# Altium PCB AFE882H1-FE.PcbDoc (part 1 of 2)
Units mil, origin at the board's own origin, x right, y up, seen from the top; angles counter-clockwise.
Board outline 2755.91 x 1181.1 mil, 4 copper layers (Top Layer, Int1 (GND), Int2 (PWR), Bottom Layer), stack 53.912 mil thick; 80 components, 47 nets, 216 pads, 76 vias.
Unrouted connection lines stored in the file: 4.
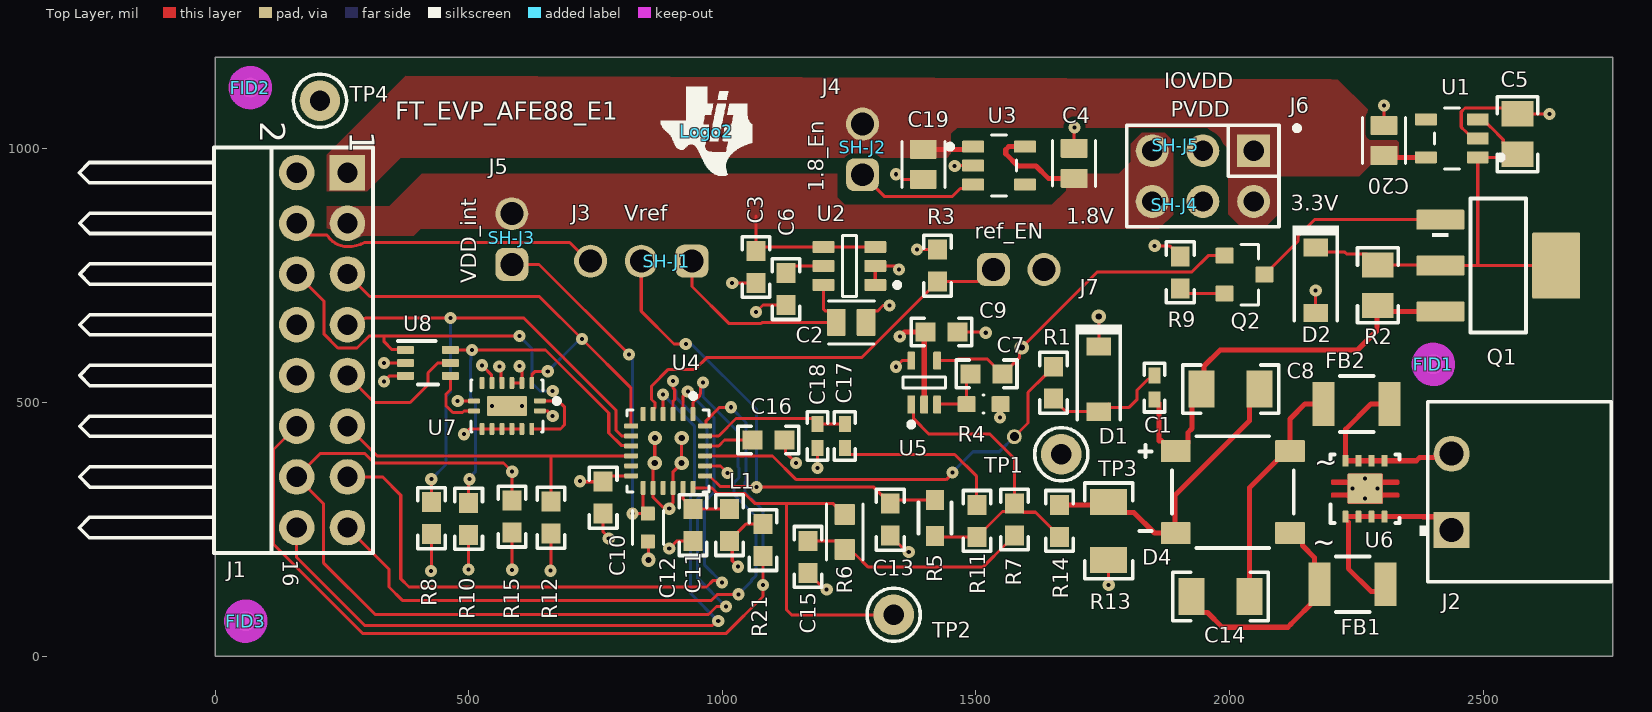
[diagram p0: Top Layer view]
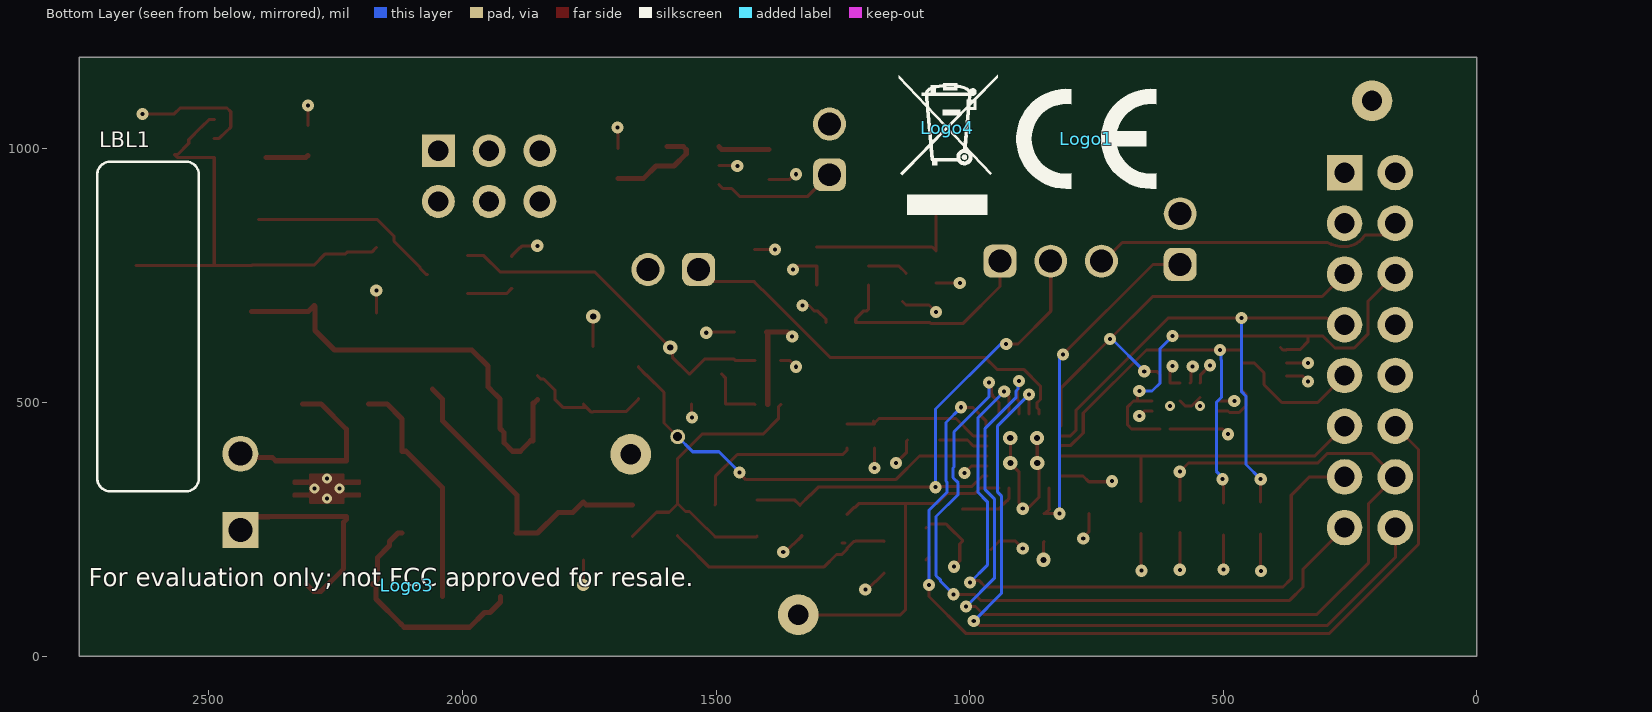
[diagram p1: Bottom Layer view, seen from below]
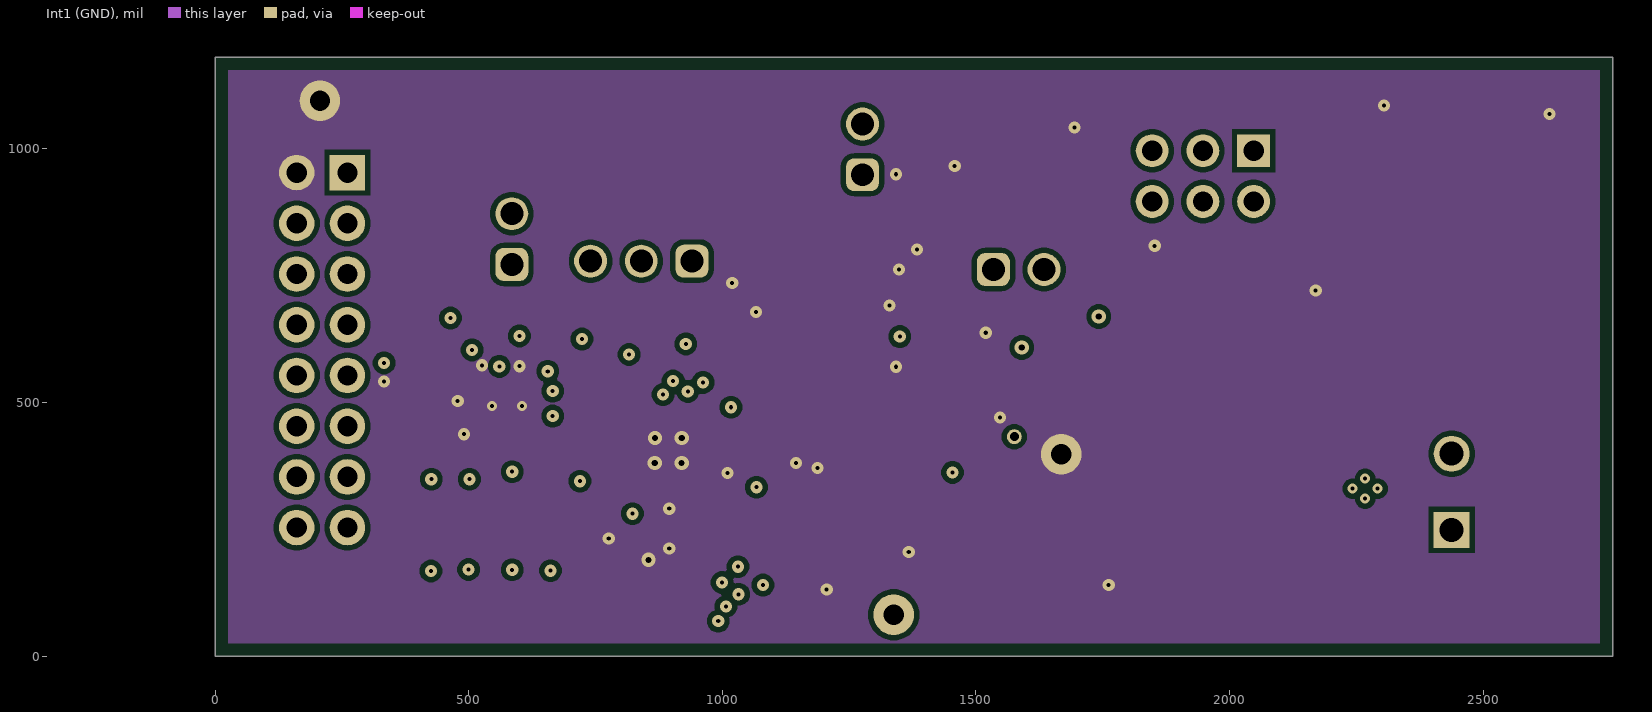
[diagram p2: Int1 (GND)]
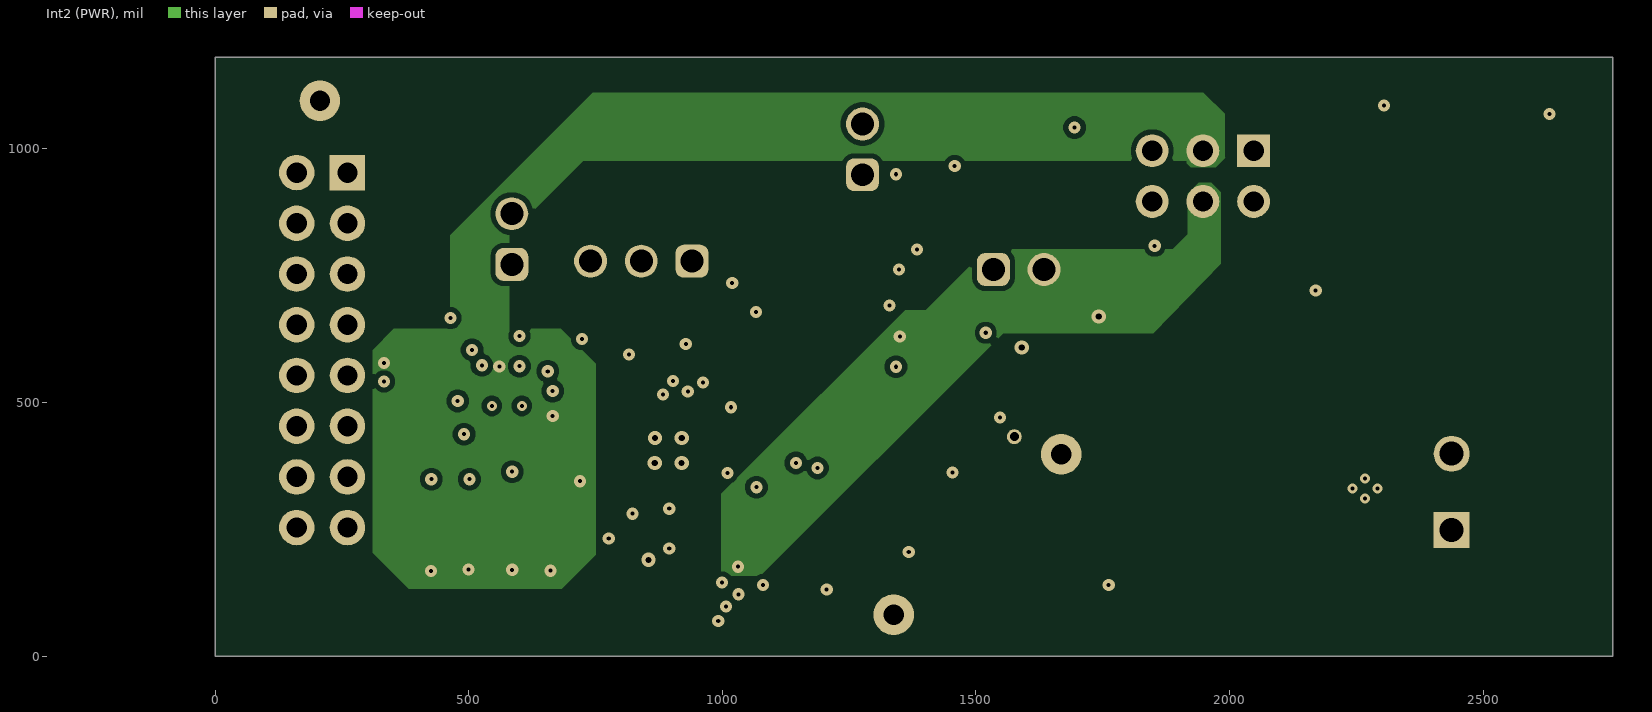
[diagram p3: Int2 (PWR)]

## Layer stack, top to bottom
Top Solder: solder mask 1, SM-001, Dk 4
Top Layer: signal copper 1.378
Dielectric 1: prepreg 5.1, PP-017, Dk 4.3
Dielectric 2: prepreg 5.1, PP-017, Dk 4.3
Int1 (GND): signal copper 1.378
Dielectric 3: core 28, Core-039, Dk 4.8
Int2 (PWR): signal copper 1.378
Dielectric 4: prepreg 5.1, PP-017, Dk 4.3
Dielectric 5: prepreg 5.1, PP-017, Dk 4.3
Bottom Layer: signal copper 1.378
Bottom Solder: solder mask 1, SM-001, Dk 4

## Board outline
0,0 2755.91,0 2755.91,1181.1 0,1181.1

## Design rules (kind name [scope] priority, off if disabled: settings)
AcuteAngle [All] p1 off: minimum=4.50000000000000E+0001 checktracksonly=FALSE
AssemblyTestPointUsage [All] p1: valid=2
BoardOutlineClearance BoardOutlineClearance_MountingHoles [OnCopper and InComponentClass('Mounting Holes')] p1: gap=39.37 ignorepadtopadclearanceinfootprint=FALSE
BoardOutlineClearance BoardOutlineClearance_Poly [OnCopper and IsPoly] p2: gap=25 ignorepadtopadclearanceinfootprint=FALSE
BoardOutlineClearance [OnCopper and Not InComponentClass('Logo') and not InComponentClass('FiducialMark') and not InRegion(1000,500,4000,800) and not InPoly] p3: gap=40 ignorepadtopadclearanceinfootprint=FALSE
Clearance Clearance_Keepouts [((IsTrack Or IsArc) And Not InPoly) And IsFree and IsKeepOut vs ((IsTrack Or IsArc) And Not InPoly) And IsFree and IsKeepOut] p1: gap=0 ignorepadtopadclearanceinfootprint=FALSE
Clearance Clearance_Poly [InPolygon] p2: gap=10 ignorepadtopadclearanceinfootprint=TRUE
Clearance Clearance_FiducialMark [IsKeepOut and InComponentClass('FiducialMark') vs IsPad and InComponentClass('FiducialMark')] p3: gap=0 ignorepadtopadclearanceinfootprint=FALSE
Clearance [All] p4: gap=7.87 ignorepadtopadclearanceinfootprint=TRUE
ComponentClearance ComponentClearance_MountingHoles_FiducialMarks [InComponentClass('Mounting Holes') vs InComponentClass('FiducialMark')] p1: gap=50 collisioncheckmode=3 verticalgap=10 showdistances=FALSE
ComponentClearance ComponentClearance_Shunt [InComponentClass('Header') vs InComponentClass('Shunt')] p2: gap=0 collisioncheckmode=3 verticalgap=0 showdistances=FALSE
ComponentClearance ComponentClearance_Logo [InComponentClass('Logo')] p3: gap=30 collisioncheckmode=3 verticalgap=10 showdistances=FALSE
ComponentClearance ComponentClearance_ScrewToNut [(HasFootprint('NY PMS 440 0025 PH')) vs (HasFootprint('Keystone_1902C'))] p4: gap=5 collisioncheckmode=3 verticalgap=10 showdistances=FALSE
ComponentClearance ComponentClearance_MountingHoles [InComponentClass('Mounting Holes')] p5: gap=100 collisioncheckmode=3 verticalgap=100000 showdistances=FALSE
ComponentClearance ComponentClearance_SmallPassives [HasFootprint('0201*') or HasFootprint('0402*') or HasFootprint('0508') or HasFootprint('0603*') or HasFootprint('0612') or HasFootprint('0805*') or HasFootprint('0815*') or HasFootprint('0830*') or HasFootprint('1206*') or HasFootprint('1210*') or HasFootprint('1808*') or HasFootprint('1812*') or HasFootprint('1825*') or HasFootprint('2010*') or HasFootprint('2220*') or HasFootprint('2225*') or HasFootprint('2512*') or HasFootprint('2728*') or HasFootprint('3518*') vs HasFootprint('0201*') or HasFootprint('0402*') or HasFootprint('0508') or HasFootprint('0603*') or HasFootprint('0612') or HasFootprint('0805*') or HasFootprint('0815*') or HasFootprint('0830*') or HasFootprint('1206*') or HasFootprint('1210*') or HasFootprint('1808*') or HasFootprint('1812*') or HasFootprint('1825*') or HasFootprint('2010*') or HasFootprint('2220*') or HasFootprint('2225*') or HasFootprint('2512*') or HasFootprint('2728*') or HasFootprint('3518*')] p6: gap=14.96 collisioncheckmode=3 verticalgap=10 showdistances=FALSE
ComponentClearance ComponentClearance_THtoSMT [IsThruComponent vs IsSMTComponent] p7: gap=30 collisioncheckmode=3 verticalgap=30 showdistances=FALSE
ComponentClearance ComponentClearance_THtoTH [IsThruComponent vs IsThruComponent] p8: gap=20 collisioncheckmode=3 verticalgap=30 showdistances=FALSE
ComponentClearance [All] p9: gap=20 collisioncheckmode=3 verticalgap=10 showdistances=FALSE
DiffPairsRouting [All] p1: maxlimit=100 minlimit=10 mostfreqgap=10 toplayer_minwidth=15 toplayer_maxwidth=15 toplayer_prefwidth=15 midlayer1_minwidth=15 midlayer1_maxwidth=15 midlayer1_prefwidth=15 midlayer2_minwidth=15 midlayer2_maxwidth=15 midlayer2_prefwidth=15 bottomlayer_minwidth=15 bottomlayer_maxwidth=15 bottomlayer_prefwidth=15 maxuncoupledlength=1000
FabricationTestPointUsage TestPointUsage [All] p1: valid=2 allowmultiple=FALSE
FabricationTestpoint Testpoint [All] p1: side=3 testpointundercomponent=TRUE minsize=40 maxsize=100 preferedsize=60 minholesize=0 maxholesize=40 preferedholesize=32 testpointgrid=1 allowsidetop=TRUE allowsidebottom=TRUE usegrid=TRUE gridtolerance=0.01
FanoutControl Fanout_LCC [IsLCC] p1: bgadir=Out bgaviamode=Centered fanoutstyle=Auto fanoutdirection=Alternating viagrid=1 // Fanout_LCC (Default Rule)
FanoutControl Fanout_BGA [IsBGA] p2: bgadir=Out bgaviamode=Centered fanoutstyle=Auto fanoutdirection=Alternating viagrid=1 // Fanout_BGA (Default Rule)
FanoutControl Fanout_Default [All] p4: bgadir=Out bgaviamode=Centered fanoutstyle=Auto fanoutdirection=Alternating viagrid=1 // Fanout_Default (Default Rule)
FanoutControl Fanout_Small [(CompPinCount < 5)] p5: bgadir=Out bgaviamode=Centered fanoutstyle=Auto fanoutdirection=OutThenIn viagrid=1 // Fanout_Small (Default Rule)
HoleSize [All] p1: absolutevalues=TRUE maxlimit=251 minlimit=7.87 maxpercent=80.000 minpercent=20.000
MinimumAnnularRing MinimumAnnularRing_ThermalPadVias [IsVia and InAnyComponent] p1: minimumring=5.91
MinimumAnnularRing [All] p2: minimumring=7.87
MinimumSolderMaskSliver MinimumSolderMaskSliver_Logo [InComponentClass('Logo') vs InComponentClass('Logo')] p1: minsoldermaskwidth=0.7
MinimumSolderMaskSliver [All] p2: minsoldermaskwidth=3.94
PlaneConnect [All] p1: planeconnectstyle=Relief reliefexpansion=10 reliefentries=4 reliefconductorwidth=10 reliefairgap=10
PolygonConnect PolygonConnect_6 [All vs IsNamedPolygon('TOP_LAYER_GND_P000')] p1: connectstyle=Direct reliefconductorwidth=10 reliefentries=4 polygonreliefangle="90 Angle" airgapwidth=10
PolygonConnect PolygonConnect_5 [All vs IsNamedPolygon('TOP_LAYER_GND_P000')] p2: connectstyle=Direct reliefconductorwidth=10 reliefentries=4 polygonreliefangle="90 Angle" airgapwidth=10
PolygonConnect PolygonConnect_4 [All vs IsNamedPolygon('TOP_LAYER_GND_P001')] p3: connectstyle=Direct reliefconductorwidth=10 reliefentries=4 polygonreliefangle="90 Angle" airgapwidth=10
PolygonConnect PolygonConnect_3 [All vs IsNamedPolygon('TOP_LAYER_GND_P001')] p4: thpad.connectstyle=Direct thpad.reliefconductorwidth=10 thpad.reliefentries=4 thpad.polygonreliefangle="90 Angle" thpad.airgapwidth=10 smdpad.connectstyle=Direct smdpad.reliefconductorwidth=10 smdpad.reliefentries=4 smdpad.polygonreliefangle="90 Angle" smdpad.airgapwidth=10 via.connectstyle=Relief via.reliefconductorwidth=10 via.reliefentries=4 via.polygonreliefangle="90 Angle" via.airgapwidth=10
PolygonConnect PolygonConnect_2 [All vs IsNamedPolygon('TOP_LAYER_NONET_P000')] p5: thpad.connectstyle=Direct thpad.reliefconductorwidth=10 thpad.reliefentries=4 thpad.polygonreliefangle="90 Angle" thpad.airgapwidth=10 smdpad.connectstyle=Direct smdpad.reliefconductorwidth=10 smdpad.reliefentries=4 smdpad.polygonreliefangle="90 Angle" smdpad.airgapwidth=10 via.connectstyle=Relief via.reliefconductorwidth=10 via.reliefentries=4 via.polygonreliefangle="90 Angle" via.airgapwidth=10
PolygonConnect PolygonConnect_1 [All vs IsNamedPolygon('TOP_LAYER_NONET_P000')] p6: thpad.connectstyle=Direct thpad.reliefconductorwidth=10 thpad.reliefentries=4 thpad.polygonreliefangle="90 Angle" thpad.airgapwidth=10 smdpad.connectstyle=Direct smdpad.reliefconductorwidth=10 smdpad.reliefentries=4 smdpad.polygonreliefangle="90 Angle" smdpad.airgapwidth=10 via.connectstyle=Relief via.reliefconductorwidth=10 via.reliefentries=4 via.polygonreliefangle="90 Angle" via.airgapwidth=10
PolygonConnect [All] p7: connectstyle=Direct reliefconductorwidth=10 reliefentries=4 polygonreliefangle="90 Angle" airgapwidth=10
RoutingLayers [All] p1: top layer_v5=TRUE mid layer 1_v5=FALSE mid layer 2_v5=FALSE bottom layer_v5=TRUE
RoutingVias ThermalPadVias [IsVia and InAnyComponent] p1: holewidth=7.87 width=19.68 viastyle="Through Hole" minholewidth=7.87 minwidth=19.68 maxholewidth=12.99 maxwidth=23.62
RoutingVias [All] p2: holewidth=16 width=34 viastyle="Through Hole" minholewidth=7.87 minwidth=24 maxholewidth=40 maxwidth=65
SilkToBoardRegionClearance [Not ((IsComment or IsDesignator) And (Hide <> 'False')) and not InRegion(1000,500,4000,800)] p1:
SilkToSilkClearance SilkToSilkClearance_Pb-FreeLogo [(HasFootprint('Pb-Free_Overlay_Medium') OR HasFootprint('Pb-Free_Overlay_Small')) vs (HasFootprint('Pb-Free_Overlay_Medium') OR HasFootprint('Pb-Free_Overlay_Small'))] p1 off: silktosilkclearance=0
SilkToSilkClearance [All] p2: silktosilkclearance=3.94
SilkToSolderMaskClearance SilkToComponentPadClearance [(IsPad or IsFill or IsRegion) and InAnycomponent] p1 off: minsilkscreentomaskgap=5 clearancetoexposedcopper=TRUE
SilkToSolderMaskClearance "Silk to Solder Mask Opening" [All] p2 off: minsilkscreentomaskgap=3.94 clearancetoexposedcopper=FALSE
SolderMaskExpansion [All] p1: expansion=1.97 istentingtop=FALSE
UnRoutedNet [All] p1: checkbadconnections=TRUE
Width [All] p1: maxlimit=100 minlimit=6 preferedwidth=6 minimp=50.000000 maximp=50.000000 favimp=50.000000 checkconnectedcopper=TRUE
13 further rules are at their usual default settings.

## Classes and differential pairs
component class Shunt: SH-J1 SH-J2 SH-J3 SH-J4 SH-J5
component class Logo: Logo2
component class Header: J1 J3 J4 J5 J6 J7
component class AFE882H1-FE_BlankSheet: C1 C2 C3 C4 C5 C6 C7 C8 C9 C10 C11 C12 C13 C14 C15 C16 C17 C18 C19 C20 D1 D2 D4 FB1 FB2 J1 J2 J3 J4 J5 J6 J7 L1 Q1 Q2 R1 R2 R3 R4 R5 R6 R7 R8 R9 R10 R11 R12 R13 R14 R15 R21 SH-J1 SH-J2 SH-J3 SH-J4 SH-J5 TP1 TP2 TP3 U1 U2 U3 U4 U5 U6 U7 U8
component class AFE882H1-FE_Hardware: FID1 FID2 FID3 H9 LBL1 Logo1 Logo2 Logo3 Logo4 ZZ1 ZZ2 ZZ3 ZZ4
component class FiducialMark: FID1 FID2 FID3
component class AssemblyNote: ZZ1 ZZ2 ZZ3 ZZ4
component class Label: LBL1

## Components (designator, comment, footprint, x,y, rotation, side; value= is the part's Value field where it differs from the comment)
C1 "CGA2B2X7R1H222K050BA" 0402 1852.08,529.31 r270 top value=2200pF
C2 "C0805C105J4RAC" FP-C0805C105J4RAC_0805-MFG 1254,657.91 r180 top value=1µF
C3 "06033C104JAT2A" 0603 1065.98,767.36 r270 top value=0.1uF
C4 "C0805C105J4RAC" FP-C0805C105J4RAC_0805-MFG 1693.54,971.67 r270 top value=1µF
C5 "TMK212B7225KG-TR" 0805_HV 2568.24,1029.32 r90 top value=2.2uF
C6 "06033C104JAT2A" 0603 1125.37,723.78 r270 top value=0.1uF
C7 "06035A221FAT2A" 0603 1520.89,556.69 r180 top value=220pF
C8 "C1206C102K5RACTU" 1206 2002.2,526.41 r0 top value=1000pF
C9 "06033C104JAT2A" 0603 1432.04,639.21 r0 top value=0.1uF
C10 "06033C104JAT2A" 0603 764.91,312.35 r270 top value=0.1uF
C11 "06033C104JAT2A" 0603 942.2,258.34 r270 top value=0.1uF
C12 "EMK107C6105MA-T" FP-EMK107C6105MA-T_0603-MFG 852.92,253.51 r90 top
C13 "06033C104JAT2A" 0603 1330.98,269.07 r270 top value=0.1uF
C14 "12061A102FAT2A" 1206 1982.29,117.43 r0 top value=1000pF
C15 "885012206091" 0603 1168.79,195.62 r270 top value=0.022uF
C16 "C0603C681J5GACTU" 0603 1090.76,426.04 r180 top value=680pF
C17 "885012205061" 0402 1241.35,434.08 r90 top value=1000pF
C18 "885012205061" 0402 1187.5,434.08 r90 top value=1000pF
C19 "C0805C105J4RAC" FP-C0805C105J4RAC_0805-MFG 1396.01,969.7 r90 top value=1µF
C20 "C0805C105J4RAC" FP-C0805C105J4RAC_0805-MFG 2304.77,1016.88 r270 top value=1µF
D1 "1N4148W-TP" SOD-123 1742.42,546.14 r270 top value=100V
D2 "MMSZ4688-HE3-08" SOD-123 2169.93,741.08 r270 top value=4.7V
D4 "CD-MBL206SL" CD-MBL2xxS 2006.58,323.3 r0 top value=600V
FB1 "FBMH3225HM601NT" 1210_280 2242.72,141.69 r0 top value="600 ohm"
FB2 "FBMH3225HM601NT" 1210_280 2250.55,497.39 r0 top value="600 ohm"
FID1 "Fiducial" Fiducial10-20 2402.05,575.39 r0 top
FID2 "Fiducial" Fiducial10-20 68.9,1121.1 r0 top
FID3 "Fiducial" Fiducial10-20 60,68.9 r0 top
J1 "DUT_CONN" GPSI16 210.52,603.39 r270 top
J2 "1803277" PhoenixContact_1803277 2438.1,324.08 r90 top
J3 "61300311121" WURTH_61300311121 840,778.76 r180 top
J4 "61300211121" WURTH_61300211121 1276.3,999.23 r90 top
J5 "61300211121" WURTH_61300211121 584.69,822.34 r90 top
J6 "TSW-103-07-G-D" TSW-103-07-G-D 1947.52,946.51 r180 top
J7 "61300211121" WURTH_61300211121 1584.31,762.34 r0 top
L1 "MLZ1608N100LT000" 0603 1013.72,258.34 r270 top value=10uH
LBL1 "THT-14-423-10" Label_650x200 2620,650 r90 bottom
Logo1 "CE Mark" CE_Mark_5mm 770,1020 r180 bottom
Logo2 "Texas Instruments" TI_Symbol_Overlay_Small 968.54,1034.76 r0 top
Logo3 "FCC disclaimer" FCC_disclaimer 2110,140 r180 bottom
Logo4 "WEEE logo" WEEE_Minimum 1044.25,1042.16 r180 bottom
Q1 "PZT2907A" SOT-223 2530,770 r0 top value="60 V"
Q2 "SMMBT3904LT3G" FP-SMMBT3904LT3G_SOT23-MFG 2029.53,752.17 r0 top value=40V
R1 "RC0603JR-071KL" 0603 1653.07,539.09 r270 top value=1.0k
R2 "RG2012P-123-B-T5" 0805_HV 2292.33,731.24 r270 top value=12.0k
R3 "RC0603FR-072M21L" 0603 1424.49,770 r90 top value=2.21Meg
R4 "RC0603FR-0720KL" FP-RC0603FR-0720KL_0603-MFG 1515.18,496.91 r0 top value=20k
R5 "RN73C1J412KBTDF" FP-RN731J-MFG 1419,272.03 r270 top value=412KΩ
R6 "RC0603FR-0720KL" FP-RC0603FR-0720KL_0603-IPC_A 1241.35,244.56 r90 top value=20k
R7 "RC0603FR-07100KL" 0603 1575.87,269.27 r90 top value=100k
R8 "M55342K12B10E0T" 0603 426.01,272.03 r270 top value=10.0k
R9 "RT0603BRD074K99L" 0603 1902.81,756.83 r270 top value=4.99k
R10 "M55342K12B10E0T" 0603 499.61,270.68 r270 top value=10.0k
R11 "RT0603DRE07499KL" 0603 1502.18,266.55 r270 top value=499k
R12 "M55342K12B10E0T" 0603 661.65,273.08 r270 top value=10.0k
R13 "CRCW120620R0FKEAHP" 1206 1761.77,246.86 r270 top value=20.0
R14 "RG1608P-203-B-T5" 0603 1665,266.55 r270 top value=20.0k
R15 "M55342K12B10E0T" 0603 584.84,275.16 r270 top value=10.0k
R21 "M55342K12B10E0T" 0603 1080,228.81 r90 top value=10.0k
SH-J1 "60900213421" Wurth_60900213421 890.51,778.76 r180 top
SH-J2 "60900213421" Wurth_60900213421 1276.3,1002.95 r90 top
SH-J3 "60900213421" Wurth_60900213421 584.69,825.05 r90 top
SH-J4 "60900213421" Wurth_60900213421 1892.4,889.6 r180 top
SH-J5 "60900213421" Wurth_60900213421 1893.98,1007.68 r180 top
TP1 "TP_H0.45P0.75" TP_H045P075 1575.55,432.57 r0 top
TP2 "VOUT" Keystone5002 1337.73,81.48 r90 top
TP3 "GND" Keystone5002 1668.3,398.01 r90 top
TP4 "GND" Keystone5002 206.4,1095.28 r90 top
U1 "TPS7A0333DBVR" DBV0005A-MFG 2438.34,1020.88 r180 top
U2 "REF35125QDBVR" DBV0006A-MFG 1250.25,769.32 r180 top
U3 "TPS7A0318DBVR" DBV0005A-MFG 1545.53,967.14 r0 top
U4 "AFE882H1RRUT" RRU0024A-MFG 892.98,404.55 r270 top
U5 "OPA391DCKT" DCK0005A-MFG 1397.97,539.29 r90 top
U6 "TVS3301DRBR" DRB0008A 2267.33,330.1 r90 top
U7 "SN74LV8T165BQBR" BQB0016A-MFG 575,493.29 r270 top
U8 "TMUX1219DCKR" DCK0006A_N 419.29,578.18 r0 top
ZZ1 "This Assembly Note is for PCB labels only" AssemblyNoteLabel 185,3938 r0 top
ZZ2 "These assemblies are ESD sensitive, ESD precautions shall be observed." AssemblyNote 185,3829.11 r0 top
ZZ3 "These assemblies must be clean and free from flux and all contaminants. Use of no clean flux is not acceptable." AssemblyNote 185,3740.56 r0 top
ZZ4 "These assemblies must comply with workmanship standards IPC-A-610 Class 2, unless otherwise specified." AssemblyNote 185,3652 r0 top

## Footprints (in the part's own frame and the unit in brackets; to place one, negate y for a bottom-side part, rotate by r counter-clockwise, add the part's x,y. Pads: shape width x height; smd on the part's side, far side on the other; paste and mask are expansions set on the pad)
0402 [mm] "0402 from SM-752 data"
  rect 0.8x0.6 smd: 1(-0.6,0) 2(0.6,0)
  silkscreen extent -1.22,-0.52 1.22,0.52, body extent -0.55,-0.3 0.55,0.3, height 0.6
0603 [mm] "0603 from SM-752 data"
  rect 1x0.95 smd: 1(-0.8,0) 2(0.8,0)
  silkscreen extent -1.52,-0.69 1.52,0.69, body extent -0.87,-0.47 0.87,0.47, height 1
0805_HV [mil] "0805 with 30mil clearance between pads"
  rect 50x63 smd: 1(-40,0) 2(40,0)
  silkscreen extent -74,-40 74,40, body extent -43,-29 43,29, height 57
1206 [mm] "1206 from SM-752 data"
  rect 1.3x1.85 smd: 1(-1.45,0) 2(1.45,0)
  silkscreen extent -2.4,-1.21 2.4,1.21, body extent -1.7,-0.9 1.7,0.9, height 1.35
1210_280 [mm] "SMD, 2-Leads, Body 3.6x2.8mm, Height 2.8mm"
  rect 1.1x2.2 smd: 1(-1.65,0) 2(1.65,0)
  silkscreen extent -0.84,-1.4 0.84,1.4, body extent -1.8,-1.4 1.8,1.4, height 2.8
AssemblyNote [mil] "Assembly Note"
AssemblyNoteLabel [mil] "Assembly Note for PCB Labels"
BQB0016A-MFG [mm]
  rrect42% 0.24x0.6 smd paste+0 mask+0: 1(-0.25,1.65) 8(-0.25,-1.65) 9(0.25,-1.65) 16(0.25,1.65)
  rrect42% 0.6x0.24 smd paste+0 mask+0: 2(-1.15,1.25) 3(-1.15,0.75) 4(-1.15,0.25) 5(-1.15,-0.25) 6(-1.15,-0.75) 7(-1.15,-1.25) 10(1.15,-1.25) 11(1.15,-0.75) 12(1.15,-0.25) 13(1.15,0.25) 14(1.15,0.75) 15(1.15,1.25)
  rrect10% 1x2 smd paste-1000 mask+0: 17(0,0)
  silkscreen extent -1.3,-1.8 1.3,2.63, body extent -1.55,-2.05 1.55,2.05, height 0.25
CD-MBL2xxS [mm] "SMD, 4-Leads, Body 5.72x4.1mm"
  rrect9% 1.5x1.1 smd: 1(-2.86,2.05) 2(2.86,2.05) 3(2.86,-2.05) 4(-2.86,-2.05)
  silkscreen extent -4.67,-2.8 3.05,2.8, body extent -2.9,-2.65 2.9,2.65, height 1.02
CE_Mark_5mm [mil] "Minimum text height for CE Mark"
  silkscreen extent -138,-98 138,98
DBV0005A-MFG [mm]
  rrect17% 1.1x0.6 smd paste+0 mask+0: 1(-1.3,0.95) 2(-1.3,0) 3(-1.3,-0.95) 4(1.3,-0.95) 5(1.3,0.95)
  silkscreen extent -2.58,-1.52 0.87,1.53, body extent -1.95,-1.78 1.95,1.78, height 0.25
DBV0006A-MFG [mm]
  rrect17% 1.1x0.6 smd paste+0 mask+0: 1(-1.3,0.95) 2(-1.3,0) 3(-1.3,-0.95) 4(1.3,-0.95) 5(1.3,0) 6(1.3,0.95)
  silkscreen extent -2.53,-1.53 0.35,1.52, body extent -1.95,-1.78 1.95,1.78, height 0.25
DCK0005A-MFG [mm]
  rrect25% 0.9x0.4 smd paste-1000 mask+0: 1(-1.1,0.65) 2(-1.1,0) 3(-1.1,-0.65) 4(1.1,-0.65) 5(1.1,0.65)
  silkscreen extent -2.22,-1.07 0.27,1.08, body extent -1.65,-1.33 1.65,1.33, height 0.25
DCK0006A_N [mm] "SOT23, 6-Leads, Body 2x1.3mm, Pitch 0.65mm, Lead Span 2.1mm, IPC Medium Density"
  rrect25% 0.85x0.4 smd: 1(-1.125,0.65) 2(-1.125,0) 3(-1.125,-0.65) 4(1.125,-0.65) 5(1.125,0) 6(1.125,0.65)
  silkscreen extent -1.5,-1.09 0.51,1.09, body extent -1.14,-1 1.14,1, height 0.95
DRB0008A [mm] "VSON-8"
  rrect32% 0.6x0.31 smd: 1(-1.4,0.975) 2(-1.4,0.325) 3(-1.4,-0.325) 4(-1.4,-0.975) 5(1.4,-0.975) 6(1.4,-0.325) 7(1.4,0.325) 8(1.4,0.975)
  rrect7% 1.5x1.75 smd paste-0.75: 9(0,0)
  Top Layer region: -0.7,-0.875 -0.49,-0.875 -0.471,-0.879 -0.455,-0.89 -0.444,-0.906 -0.44,-0.925 -0.44,-0.925 -0.44,-1.65 -0.436,-1.669 -0.425,-1.685 -0.409,-1.696 -0.39,-1.7 -0.39,-1.7 -0.26,-1.7 -0.241,-1.696 -0.225,-1.685 -0.214,-1.669 -0.21,-1.65 -0.21,-1.65 -0.21,-0.925 -0.206,-0.906 -0.195,-0.89 -0.179,-0.879 -0.16,-0.875 -0.16,-0.875 0.16,-0.875 0.179,-0.879 0.195,-0.89 0.206,-0.906 0.21,-0.925 0.21,-0.925 0.21,-1.65 0.21,-1.65 0.214,-1.669 0.225,-1.685 0.241,-1.696 0.26,-1.7 0.26,-1.7 0.39,-1.7 0.409,-1.696 0.425,-1.685 0.436,-1.669 0.44,-1.65 0.44,-1.65 0.44,-0.925 0.444,-0.906 0.455,-0.89 0.471,-0.879 0.49,-0.875 0.49,-0.875 0.7,-0.875 0.719,-0.871 0.735,-0.86 0.746,-0.844 0.75,-0.825 0.75,-0.825 0.75,0.825 0.746,0.844 0.735,0.86 0.719,0.871 0.7,0.875 0.7,0.875 0.49,0.875 0.471,0.879 0.455,0.89 0.444,0.906 0.44,0.925 0.44,0.925 0.44,1.65 0.436,1.669 0.425,1.685 0.409,1.696 0.39,1.7 0.39,1.7 0.26,1.7 0.241,1.696 0.225,1.685 0.214,1.669 0.21,1.65 0.21,1.65 0.21,1.65 0.21,0.925 0.206,0.906 0.195,0.89 0.179,0.879 0.16,0.875 0.16,0.875 -0.16,0.875 -0.179,0.879 -0.195,0.89 -0.206,0.906 -0.21,0.925 -0.21,0.925 -0.21,1.65 -0.214,1.669 -0.225,1.685 -0.241,1.696 -0.26,1.7 -0.26,1.7 -0.39,1.7 -0.409,1.696 -0.425,1.685 -0.436,1.669 -0.44,1.65 -0.44,1.65 -0.44,0.925 -0.444,0.906 -0.455,0.89 -0.471,0.879 -0.49,0.875 -0.49,0.875 -0.7,0.875 -0.719,0.871 -0.735,0.86 -0.746,0.844 -0.75,0.825 -0.75,0.825 -0.75,-0.825 -0.746,-0.844 -0.735,-0.86 -0.719,-0.871 -0.7,-0.875
  silkscreen extent -1.73,-1.73 1.73,1.73, body extent -1.5,-1.5 1.5,1.5, height 0.77
FCC_disclaimer [mil]
Fiducial10-20 [mm]
  round 1 smd mask+0.5: 1(0,0)
  Top Layer keep-out circle w1.178: c0,0 r0.5
FP-C0805C105J4RAC_0805-MFG [mm]
  rrect11% 0.95x1.35 smd paste+0 mask+0: 1(-0.75,0) 2(0.75,0)
  silkscreen extent -1.15,-1.08 1.15,1.08, body extent -1.4,-0.85 1.4,0.85, height 0.25
FP-EMK107C6105MA-T_0603-MFG [mm]
  rrect14% 0.7x0.7 smd paste+0 mask+0: 1(-0.7,0) 2(0.7,0)
  silkscreen extent -0.85,-0.77 0.85,0.77, body extent -1.15,-0.55 1.15,0.55, height 0.25
FP-RC0603FR-0720KL_0603-IPC_A [mil]
  rrect10% 41.68x39.85 smd paste+0 mask+0: 1(-34.52,0) 2(34.52,0)
  silkscreen extent -55,-36 55,36, body extent -75,-40 75,40, height 10
FP-RC0603FR-0720KL_0603-MFG [mm]
  rrect13% 0.9x0.8 smd paste+0 mask+0: 1(-0.85,0) 2(0.85,0)
  silkscreen extent -0.03,-0.45 0.02,0.45, body extent -1.4,-0.55 1.4,0.55, height 0.25
FP-RN731J-MFG [mm]
  rect 1x0.9 smd paste+0 mask+0: 1(-0.9,0) 2(0.9,0)
  silkscreen extent -0.78,-0.83 0.77,0.83, body extent -1.5,-0.55 1.5,0.55, height 0.25
FP-SMMBT3904LT3G_SOT23-MFG [mm]
  rrect13% 0.9x0.8 smd paste+0 mask+0: 1(-1,0.95) 2(-1,-0.95) 3(1,0)
  silkscreen extent -0.18,-1.52 0.7,1.52, body extent -1.55,-1.62 1.55,1.62, height 0.25
GPSI16 [mil] "Samtec Right Angle Header, pins flipped from convention"
  rect 70x70 hole 40: 1(-350,50)
  round 70 hole 40: 2(-350,-50) 3(-250,50) 4(-250,-50) 5(-150,50) 6(-150,-50) 7(-50,50) 8(-50,-50) 9(50,50) 10(50,-50) 11(150,50) 12(150,-50) 13(250,50) 14(250,-50) 15(350,50) 16(350,-50)
  silkscreen extent -400,-479 400,100, body extent -400,-440 400,63, height 219
Keystone5002 [mil] "For Keystone 500x miniature loop terminals"
  round 80 hole 40: 1(0,0)
  silkscreen extent -52,-52 52,52, body extent -49,-49 49,49, height 182
Label_650x200 [mil] "Thermal Transfer Label"
  round 1 on Mech14: 0(0,0)
  silkscreen extent -325,-100 325,100, body extent -325,-100 325,100, height 1
PhoenixContact_1803277 [mm] "Phoenix Contact"
  rect 1.8x1.8 hole 1.2: 1(-1.905,0)
  round 1.8 hole 1.2: 2(1.905,0)
  silkscreen extent -4.5,-8 4.51,1.6, body extent -4.5,-8 4.51,1.3, height 7.26
RRU0024A-MFG [mm]
  rrect40% 0.7x0.25 smd paste+0 mask+0: 1(-1.85,1.25) 2(-1.85,0.75) 3(-1.85,0.25) 4(-1.85,-0.25) 5(-1.85,-0.75) 6(-1.85,-1.25) 13(1.85,-1.25) 14(1.85,-0.75) 15(1.85,-0.25) 16(1.85,0.25) 17(1.85,0.75) 18(1.85,1.25)
  rrect40% 0.25x0.7 smd paste+0 mask+0: 7(-1.25,-1.85) 8(-0.75,-1.85) 9(-0.25,-1.85) 10(0.25,-1.85) 11(0.75,-1.85) 12(1.25,-1.85) 19(1.25,1.85) 20(0.75,1.85) 21(0.25,1.85) 22(-0.25,1.85) 23(-0.75,1.85) 24(-1.25,1.85)
  silkscreen extent -2.87,-2.05 2.05,2.05, body extent -2.3,-2.3 2.3,2.3, height 0.25
SOD-123 [mm] "On Semi recommended land pattern"
  rect 0.915x1.22 smd: 1(-1.638,0) 2(1.637,0)
  silkscreen extent -2.74,-1.17 2.03,1.17, body extent -1.93,-0.9 1.93,0.9, height 1.35
SOT-223 [mm] "SOT223/SC73, 4-Leads, Body 6.5x3.5mm, Pitch 2.3mm, Lead Span 7mm, IPC Medium Density"
  rrect10% 2.4x1 smd: 1(-2.9,2.3) 2(-2.9,0) 3(-2.9,-2.3)
  rrect4% 2.4x3.3 smd: 4(2.9,0)
  silkscreen extent -3.32,-3.35 1.4,3.35, body extent -3.5,-3.25 3.5,3.25, height 1.62
TI_Symbol_Overlay_Small [mil]
  silkscreen extent -90,-88 91,88
TP_H045P075 [mm] "TP_H0.45P0.75"
  round 0.75 hole 0.45: 1(0,0)
TSW-103-07-G-D [mm] "Samtec 100mil, 2x3, 230 mil above insulator"
  rect 1.65x1.65 hole 1.016: 1(-2.54,-1.27)
  round 1.65 hole 1.016: 2(-2.54,1.27) 3(0,-1.27) 4(0,1.27) 5(2.54,-1.27) 6(2.54,1.27)
  silkscreen extent -4.84,-2.54 3.81,2.54, body extent -3.81,-2.54 3.81,2.54, height 8.38
WEEE_Minimum [mil] "WEEElie bin"
  silkscreen extent -95,-172 99,104
Wurth_60900213421 [mil] "Shunt, 2.54mm, Black"
  round 1 on Mech3: 0(0,0)
  body extent -98,-48 98,48, height 338
WURTH_61300211121 [mm] "Header, 2.54mm, 2x1, TH"
  rrect50% 1.65x1.65 hole 1.15: 1(-1.27,0)
  round 1.65 hole 1.15: 2(1.27,0)
  body extent -2.54,-1.27 2.54,1.27, height 8.54
WURTH_61300311121 [mm] "Header, 2.54mm, 3x1, TH"
  rrect50% 1.65x1.65 hole 1.15: 1(-2.54,0)
  round 1.65 hole 1.15: 2(0,0) 3(2.54,0)
  body extent -3.81,-1.27 3.81,1.27, height 8.54

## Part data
C1: library part CMP-0006317-2, "CAP, CERM, 2200 pF, 50 V, +/- 10%, X7R, AEC-Q200 Grade 1, 0402", Cap_Case=0402, Manufacturer=TDK, Supplier Part Number 1=445-5606-1-ND, TempCo=X7R, Tolerance_%=10%, Value1="1.07794 ohm", Value2=50V, ValueDisplayed=2200pF
C2 C4 C19 C20: library part CMP-0096191-1, "1 µF ±5% 16V Ceramic Capacitor X7R 0805 (2012 Metric)", Manufacturer=KEMET, Operating Temperature Range="-55°C to +125°C", TempCo=15%, Temperature Characteristic=X7R, Tolerance_%=5%, ValueDisplayed=1uF
C3 C6 C9 C10 C11 C13: library part CMP-0006752-5, "CAP, CERM, 0.1 uF, 25 V, +/- 5%, X7R, 0603", Cap_Case=0603, Manufacturer=AVX, Supplier Part Number 1=478-3713-1-ND, TempCo=X7R, Tolerance_%=5%, Value1="0.05 ohm", Value2=25V, ValueDisplayed=0.1uF
C5: library part CMP-0080705-2, "CAP, CERM, 2.2 µF, 25 V,+/- 10%, X7R, 0805", Cap_Case=0805, Manufacturer="Taiyo Yuden", Supplier Part Number 1=587-2991-1-ND, TempCo=X7R, Tolerance_%=10%, Value2=25V, ValueDisplayed=2.2µF
C7: library part CMP-0006776-4, "CAP, CERM, 220 pF, 50 V, +/- 1%, C0G/NP0, 0603", Cap_Case=0603, Manufacturer=AVX, Supplier Part Number 1=478-3719-1-ND, TempCo=C0G/NP0, Tolerance_%=1%, Value1="0.083 ohm", Value2=50V, ValueDisplayed=220pF
C8: library part CMP-0008577-2, "CAP, CERM, 1000 pF, 50 V, +/- 10%, X7R, 1206", Cap_Case=1206, Manufacturer=Kemet, Supplier Part Number 1=399-1221-1-ND, TempCo=X7R, Tolerance_%=10%, Value1="0.426 ohm", Value2=50V, ValueDisplayed=1000pF
C12: library part CMP-0089439-1, "1µF ±20% 16V Ceramic Capacitor X6S 0603 (1608 Metric)", Digikey Part Number=EMK107C6105MA-T-ND, Manufacturer="Taiyo Yuden", Mouser Part Number=963-EMK107C6105MA-T, Operating Temperature Range="-55°C to +105°C", TempCo=22%, Temperature Characteristic=X6S, Tolerance_%=20%, ValueDisplayed=1uF
C14: library part CMP-0008464-3, "CAP, CERM, 1000 pF, 100 V, +/- 1%, C0G/NP0, 1206", Cap_Case=1206, Manufacturer=AVX, Supplier Part Number 1=478-3778-1-ND, TempCo=C0G/NP0, Tolerance_%=1%, Value1="0.238 ohm", Value2=100V, ValueDisplayed=1000pF
C15: library part CMP-0006836-4, "CAP, CERM, 0.022 uF, 50 V, +/- 10%, X7R, 0603", Cap_Case=0603, Manufacturer="Wurth Elektronik", TempCo=X7R, Tolerance_%=10%, Value1=Unknown, Value2=50V, ValueDisplayed=0.022uF
C16: library part CMP-0006959-4, "CAP, CERM, 680 pF, 50 V, +/- 5%, C0G/NP0, 0603", Cap_Case=0603, Manufacturer=Kemet, Supplier Part Number 1=399-3289-1-ND, TempCo=C0G/NP0, Tolerance_%=5%, Value1=Unknown, Value2=50V, ValueDisplayed=680pF
C17 C18: library part CMP-0006231-2, "CAP, CERM, 1000 pF, 50 V, +/- 10%, X7R, 0402", Cap_Case=0402, Manufacturer="Wurth Elektronik", Supplier Part Number 1=732-7556-1-ND, TempCo=X7R, Tolerance_%=10%, Value1=Unknown, Value2=50V, ValueDisplayed=1000pF
D1: library part CMP-0076974-2, "Diode, Switching, 100 V, 0.15 A, SOD-123", Manufacturer="Micro Commercial Components", Value1=0.15A, Value2=1.25V
D2: library part CMP-0077561-3, "Diode, Zener, 4.7 V, 500 mW, AEC-Q101, SOD-123", Manufacturer=Vishay-Semiconductor, Power_W=500mW, Value1=0.5W
D4: library part CMP-0067544-2, "Diode, P-N-Bridge, 600 V, 2 A, 5.8x5.3mm", Manufacturer=Bourns, Value1=2A, Value2=0.96V
FB1 FB2: library part CMP-0003374-1, "Ferrite Bead, 600 ohm @ 100 MHz, 3 A, 1210", Manufacturer="Taiyo Yuden", Supplier Part Number 1=587-1755-1-ND, Value1="0.042 ohm", Value2=3A, ValueDisplayed="600 ohm"
FID1 FID2 FID3: library part CMP-0077181-1, "Fiducial mark.  There is nothing to buy or mount.", Manufacturer=N/A
J1: library part CMP-0075420-1, "Header, 100mil, 8x2, Gold, R/A, TH", Color=Black, Current_A=6.3A, Manufacturer=Samtec, PartNumber=TSW-108-08-G-D-RA, Supplier Part Number 1=SAM1037-08-ND, Voltage_V=550V
J2: library part CMP-0055494-1, "Terminal Block, 2x1, 3.81mm, R/A, TH", Manufacturer="Phoenix Contact", Supplier Part Number 1=277-1206-ND
J3: library part CMP-0054796-4, "Header, 2.54 mm, 3x1, Gold, TH", Manufacturer="Wurth Elektronik", Supplier Part Number 1=732-5316-ND
J4 J5 J7: library part CMP-0054794-2, "Header, 2.54 mm, 2x1, Gold, TH", Color=Black, Manufacturer="Wurth Elektronik", Supplier Part Number 1=732-5315-ND
J6: library part CMP-0075406-2, "Header, 100mil, 3x2, Gold, TH", Color=Black, Current_A=6.3A, Manufacturer=Samtec, Supplier Part Number 1=SAM1028-03-ND, Voltage_V=550V
L1: library part CMP-0062720-2, "Inductor, Multilayer, Ferrite, 10 uH, 0.3 A, 0.6 ohm, SMD", Manufacturer=TDK, Supplier Part Number 1=445-6755-1-ND, Value1="0.6 ohm", Value2=0.3A, ValueDisplayed=10uH
LBL1: library part CMP-0003625-1, "Thermal Transfer Printable Labels, 0.650\" W x 0.200\" H - 10,000 per roll", Manufacturer=Brady, Supplier Part Number 1=97C5133
Logo1: library part CMP-0074844-1
Logo2: library part CMP-0074838-1, "Texas Instrument Corporate Signature"
Logo3: library part CMP-0074847-1, "FCC_disclaimer"
Logo4: library part CMP-0074769-1
Q1: library part CMP-0000355-2, "Transistor, PNP, 60 V, 0.8 A, SOT-223", Manufacturer="Fairchild Semiconductor", Supplier Part Number 1=PZT2907ACT-ND, Value1="0.8 A", Value2=300
Q2: library part CMP-0097440-1, "Bipolar (BJT) Transistor NPN 40 V 200 mA 300MHz 300 mW Surface Mount SOT-23-3 (TO-236)", Collector Base Voltage=60V, Digikey Part Number=SMMBT3904LT3GOSCT-ND, Emitter Base Voltage=6V, Manufacturer="On Semiconductor", Mouser Part Number=863-SMMBT3904LT3G, Operating Temperature Range="-55°C to +150°C", Power_W=225mW, Unity Gain Freq=300MHz
R1: library part CMP-0025899-5, "RES, 1.0 k, 5%, 0.1 W, 0603", Manufacturer=Yageo, Power_W=100mW, Supplier Part Number 1=311-1.0KGRCT-ND, TempCo="100 ppm/C", Tolerance_%=5%, Value2=0.1W, Value_Code=1k00, ValueDisplayed=1.0k
R2: library part CMP-0018871-2, "RES, 12.0 k, 0.1%, 0.125 W, 0805", Manufacturer="Susumu Co Ltd", Power_W=125mW, Supplier Part Number 1=RG20P12.0KBCT-ND, TempCo="25 ppm/C", Tolerance_%=0.1%, Value2=0.125W, Value_Code=12k0, ValueDisplayed=12.0k
R3: library part CMP-0023001-4, "RES, 2.21 M, 1%, 0.1 W, 0603", Manufacturer=Yageo, Power_W=100mW, Supplier Part Number 1=311-2.21MHRCT-ND, TempCo="100 ppm/C", Tolerance_%=1%, Value2=0.1W, Value_Code=2M21, ValueDisplayed=2.21M
R4 R6: library part CMP-0001644-1, "Res General Purpose Thick Film 0603 20K Ohm 1% 1/10W ±100ppm/°C Molded SMD Paper T/R", Approved Alternate Part Number=541-1.00HHCT-ND, Digikey Part Number=311-20.0KHRCT-ND, Manufacturer=Yageo, Mouser Part Number=603-RC0603FR-0720KL, Operating Temperature Range="-55°C to +155°C", Power=100mW, TempCo=100ppm/°C, Tolerance_%=1%, Voltage=75V
R5: library part CMP-03211-003444-1, "Thin Film Resistors RN 0603 412KΩ 0.1% 10ppm/°C", Manufacturer="TE Connectivity", Package=RN731J, Power Rating=0.063W, Resistance=412KΩ, Temperature="-55°C to +155°C", Temperature Coefficient=10ppm/°C, Temperature Range High=+155°C, Temperature Range Low=-55°C, Tolerance=0.1%, Voltage Rating=50V
R7: library part CMP-0022735-5, "RES, 100 k, 1%, 0.1 W, 0603", Manufacturer=Yageo, Power_W=100mW, Supplier Part Number 1=311-100KHRCT-ND, TempCo="100 ppm/C", Tolerance_%=1%, Value2=0.1W, Value_Code=100k
R8 R10 R12 R15 R21: library part CMP-0080488-1, "RES, 10.0 k, 1%, 0.1 W, 0603", Manufacturer="TT Electronics/IRC", Power_W=100mW, TempCo="100 ppm/C", Tolerance_%=1%, Value2=0.1W, Value_Code=10k0, ValueDisplayed=10.0k
R9: library part CMP-0024304-2, "RES, 4.99 k, 0.1%, 0.1 W, 0603", Manufacturer="Yageo America", Power_W=100mW, TempCo="25 ppm/C", Tolerance_%=0.1%, Value2=0.1W, Value_Code=4k99, ValueDisplayed=4.99k
R11: library part CMP-0025329-3, "RES, 499 k, 0.5%, 0.1 W, 0603", Manufacturer="Yageo America", Power_W=100mW, TempCo="50 ppm/C", Tolerance_%=0.5%, Value2=0.1W, Value_Code=499k
R13: library part CMP-0016782-3, "RES, 20.0, 1%, 0.5 W, AEC-Q200 Grade 0, 1206", Manufacturer=Vishay-Dale, Power_W=500mW, Supplier Part Number 1=541-20.0UCT-ND, TempCo="100 ppm/C", Tolerance_%=1%, Value2=0.5W, Value_Code=20R0, ValueDisplayed=20.0
R14: library part CMP-0023464-3, "RES, 20.0 k, 0.1%, 0.1 W, 0603", Manufacturer="Susumu Co Ltd", Power_W=100mW, Supplier Part Number 1=RG16P20.0KBCT-ND, TempCo="25 ppm/C", Tolerance_%=0.1%, Value2=0.1W, Value_Code=20k0, ValueDisplayed=20.0k
SH-J1 SH-J2 SH-J3 SH-J4 SH-J5: library part CMP-0003761-2, "Shunt, 2.54mm, Gold, Black", Manufacturer="Wurth Elektronik", Supplier Part Number 1=732-2678-ND
TP1: library part CMP-0003719-1, "Testpoint", Manufacturer="Texas Instruments"
TP2 TP3 TP4: library part CMP-0055139-2, "Test Point, Miniature, White, TH", Color=White, Manufacturer="Keystone Electronics", PartNumber=5002, Supplier Part Number 1=36-5002-ND
U1: library part CMP-0123072-1, "Nanopower-IQ 200nA 200mA low-dropout (LDO) voltage regulator with fast transient response", Digikey Part Number=296-TPS7A0333DBVRCT-ND, Dropout Voltage=310mV, Manufacturer="Texas Instruments", Max Supply Voltage=6V, Min Supply Voltage=3.8V, Mouser Part Number=595-TPS7A0333DBVR, Nominal Supply Current=0.2uA, Operating Temperature Range="-40°C to +125°C", Output Voltage=3.3V
U2: library part CMP-0097920-1, "Ultra Low-Power, High-Precision Voltage Reference", Digikey Part Number=296-REF35125QDBVRTR-ND, Manufacturer="Texas Instruments", Max Supply Voltage=6V, Min Supply Voltage=1.75V, Mouser Part Number=595-REF35125QDBVR, Nominal Supply Current=0.65uA, Operating Temperature Range="-40°C to +125°C", Output Voltage=1.25V
U3: library part CMP-0123071-1, "Nanopower-IQ 200nA 200mA low-dropout (LDO) voltage regulator with fast transient response 5-SOT-23 -40 to 125", Digikey Part Number=296-TPS7A0318DBVRCT-ND, Dropout Voltage=450mV, Manufacturer="Texas Instruments", Max Supply Voltage=6V, Min Supply Voltage=2.3V, Mouser Part Number=595-TPS7A0318DBVR, Nominal Supply Current=0.2uA, Operating Temperature Range="-40°C to +125°C", Output Voltage=1.8V
U4: library part CMP-0096723-1, Manufacturer="Texas Instruments", Operating Temperature Range=to
U5: library part CMP-0094597-1, "General Purpose Amplifier 1 Circuit Rail-to-Rail SC-70-5", Digikey Part Number=296-OPA391DCKTCT-ND, Input Bias Current=0.00000001uA, Input Offset Voltage=0.06mV, Manufacturer="Texas Instruments", Max Dual Supply Voltage=2.75V, Max Supply Voltage=5.5V, Min Dual Supply Voltage=850mV, Min Supply Voltage=1.7V, Mouser Part Number=595-OPA391DCKT, Nominal Supply Current=24uA, Operating Temperature Range="-40°C to +125°C", Output Current Per Channel=60mA, Voltage Gain=121dB
U6: library part CMP-0081715-3, "33 V Bidirectional Flat-Clamp Surge Protection Device, DRB0008A (VSON-8)", Alternate Manufacturer="Texas Instruments", Alternate PartNumber=TVS3301DRBT, Operating Temperature Range="-40 to 125 C", Rating=Catalog
U7: library part CMP-0123563-1, "1.65-V to 5.5-V 8-bit parallel-load shift register with voltage translation", Digikey Part Number=296-SN74LV8T165BQBRCT-ND, Frequency_Fixed=37.7MHz, Manufacturer="Texas Instruments", Max Supply Voltage=5.5V, Min Supply Voltage=1.65V, Mouser Part Number=595-SN74LV8T165BQBR, Nominal Supply Current=2uA, Operating Temperature Range="-40°C to +125°C"
U8: library part CMP-0860319-1, "1-ch, 2:1 general-purpose analog multiplexer with 1.8-V logic control, DCK0006A (SOT-SC70-6)", Alternate Manufacturer="Texas Instruments", Operating Temperature Range="-40 to 125 C", Rating=Catalog
ZZ1: library part CMP-0003616-3
ZZ2: library part CMP-0077236-1
ZZ3: library part CMP-0077237-1
ZZ4: library part CMP-0077238-1

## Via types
v1: diameter 24, hole 8, Top Layer to Bottom Layer, tented both sides, 63 vias
v2: diameter 28, hole 12, Top Layer to Bottom Layer, tented both sides, 7 vias
v3: diameter 19.68, hole 7.87, Top Layer to Bottom Layer, 4 vias
v4: diameter 19.68, hole 7.87, Top Layer to Bottom Layer, tented both sides, 2 vias

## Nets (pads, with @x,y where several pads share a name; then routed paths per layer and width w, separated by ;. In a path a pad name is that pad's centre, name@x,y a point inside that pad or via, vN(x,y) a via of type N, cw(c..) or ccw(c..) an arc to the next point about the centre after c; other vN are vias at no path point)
AIN0: U4.15
ALARM: J1.12 R21.1 U4.24 | length 1854.5
  Top Layer w6: J1.12@160.52,453.39 114.65,407.52 114.65,220.76 291.11,44.3 1006.83,44.3 1079.96,117.43 R21.1@1080,197.31 R21.1@1080,197.31 ; U4.24@965.82,453.77 967.74,455.69 967.88,455.69 967.88,464.17 994.38,490.67 v1(1016.73,490.67) ; R21.1@1083.02,192.8 R21.1@1086.11,189.71
  Bottom Layer w6: v1(1016.73,490.67) 1046.57,460.82 1046.57,344.85 1044.25,342.52 1044.25,323.58 1079.96,287.87 v1(1079.96,140.07)
CD: J1.14 R15.1 U4.3 | length 2119.9
  Top Layer w6: R15.1@584.84,306.66 585.49,307.31 v1(585.49,363.61) 568.27,380.84 313.46,380.84 295.03,399.27 206.4,399.27 J1.14@160.52,353.39 213.09,300.83 213.09,184.35 315.44,82 972.56,82 988.41,97.85 v1(1006.83,97.85) ; U4.3@902.83,477.39 902.83,502.93 906.02,506.12 906.02,525.07 902.83,528.26 v1(902.83,542.49)
  Bottom Layer w6: v1(902.83,542.49) 904.56,540.77 904.56,526.53 908.86,522.22 908.86,509.49 969.29,449.06 969.29,328.26 951.21,310.18 951.21,153.47 v1(1006.83,97.85)
CS: J1.11 R12.1 U4.10 | length 674.1
  Top Layer w6: J1.11@260.52,453.39 319.21,394.71 661.65,394.71 ; R12.1@661.65,304.57 661.65,394.71 ; U4.10@820.15,394.71 661.65,394.71
"DAC HART RX": J1.13 U4.2 | length 1400.4
  Top Layer w6: J1.13@260.52,353.39 329.56,353.39 365.69,317.26 365.69,152.55 382.1,136.14 968.54,136.14 981.85,149.45 986.82,149.45 987.66,148.62 995.89,148.62 v1(999.33,145.17) ; U4.2@922.51,477.39 922.51,512.56 v1(931.74,521.78)
  Bottom Layer w6: v1(931.74,521.78) 983.17,470.35 983.17,322.51 965.09,304.43 965.09,179.42 v1(999.33,145.17)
